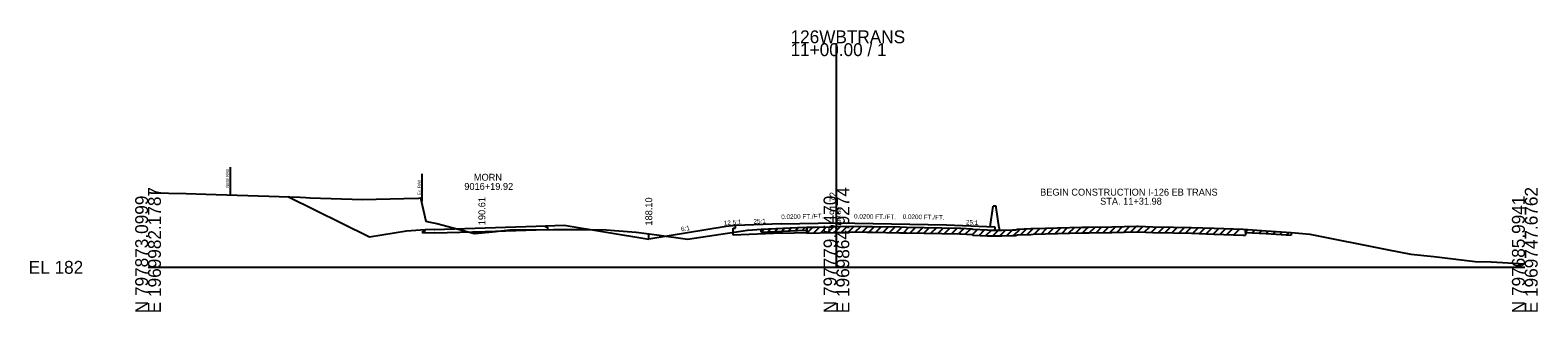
# Model space of a CAD drawing. Extents: x -6494 to 1970605, y -10 to 798140.
# Drawn here: x -25.7 to 302.8, y 3490.3 to 3551.6 of the extents above; entities that cross this region are included whole.
import ezdxf

# ---------------------------------------------------------------- set-up
doc = ezdxf.new("R2010")
doc.units = 0
for name, color, linetype in [('RD_GPK_XS_Cell', 7, 'Continuous'), ('RD_XS_Base', 7, 'Continuous'), ('RD_XS_EarthShd', 7, 'Continuous'), ('RD_XS_ExGround', 7, 'Continuous'), ('RD_XS_ExPaveRet', 7, 'Continuous'), ('RD_XS_ExRW', 7, 'Continuous'), ('RD_XS_MedBWall', 7, 'Continuous'), ('RD_XS_Misc_Line', 7, 'Continuous'), ('RD_XS_NewRW', 7, 'Continuous'), ('RD_XS_Pave', 7, 'Continuous'), ('RD_XS_PaveOvlay', 7, 'Continuous'), ('RD_XS_PaveShd', 7, 'Continuous'), ('RD_XS_TieSlope', 7, 'Continuous'), ('RD_XS_TX_Elev_EX', 7, 'Continuous'), ('RD_XS_TX_Elev_PR', 7, 'Continuous'), ('RD_XS_TX_Misc', 7, 'Continuous'), ('RD_XS_TX_Notes', 7, 'Continuous'), ('RD_XS_TX_Profile', 7, 'Continuous'), ('RD_XS_TX_ShdSlope', 7, 'Continuous'), ('RD_XS_TX_Slope', 7, 'Continuous'), ('RD_XS_TX_Station', 7, 'Continuous')]:
    doc.layers.add(name, color=color, linetype=linetype)

msp = doc.modelspace()

# ---------------------------------------------------------------- linework, layer by layer
at = {"layer": 'RD_GPK_XS_Cell'}
for p, q in [((150, 3500), (150, 3548.79)), ((0, 3500), (150, 3500)), ((150, 3500), (300, 3500))]:
    msp.add_line(p, q, dxfattribs=at)
at = {"layer": 'RD_XS_Base'}
for p, q in [((86.62, 3508.72), (86.62, 3509.02)), ((87.13, 3508.74), (86.62, 3508.72)), ((87.13, 3508.26), (87.13, 3508.74)), ((128, 3508.52), (128, 3509.08)), ((59.85, 3507.88), (60.35, 3507.89)), ((59.85, 3507.4), (59.85, 3507.88)), ((62.38, 3507.48), (59.85, 3507.4)), ((60.35, 3507.89), (60.35, 3508.19)), ((84.6, 3508.18), (87.13, 3508.26)), ((127.5, 3508.5), (128, 3508.52)), ((127.5, 3507.02), (127.5, 3508.5)), ((138, 3507.44), (127.5, 3507.02)), ((138, 3507.44), (143.58, 3507.55))]:
    msp.add_line(p, q, dxfattribs=at)
at = {"layer": 'RD_XS_EarthShd'}
for p, q in [((86.62, 3509.02), (90.66, 3509.15)), ((128, 3509.08), (126, 3508.92)), ((60.35, 3508.19), (56.31, 3507.87))]:
    msp.add_line(p, q, dxfattribs=at)
at = {"layer": 'RD_XS_ExGround'}
msp.add_lwpolyline([(0, 3516.26), (0.7, 3516.24), (8.32, 3516.06), (12.61, 3515.95), (33.13, 3515.25), (34.37, 3515.19), (35.3, 3515.16), (46.72, 3514.79), (55.7, 3514.96), (59.03, 3515.02), (59.36, 3515.16), (60.52, 3510.05), (61.1, 3509.93), (62.9, 3509.52), (71.13, 3507.33), (75.08, 3507.71), (78.85, 3508.15), (88.32, 3508.22), (90.16, 3508.22), (94.64, 3508.2), (99.82, 3508.18), (101.66, 3508.03), (106.38, 3507.63), (110.84, 3507.08), (117.51, 3506.16), (126.25, 3507.44), (130.63, 3508.1), (131.69, 3508.16), (133.57, 3508.27), (141.48, 3508.68), (149.27, 3508.84), (150, 3508.86), (153.59, 3508.95), (156.6, 3508.91), (157.85, 3508.89), (163.85, 3508.79), (165.3, 3508.77), (176.78, 3508.52), (177.11, 3508.51), (179.51, 3508.38), (179.75, 3508.27), (182.82, 3508.13), (183.33, 3508.11), (183.75, 3508.11), (186.02, 3508.1), (188.38, 3508.16), (189.02, 3508.18), (189.45, 3508.31), (192.37, 3508.43), (192.9, 3508.45), (203.49, 3508.73), (205.04, 3508.75), (210, 3508.83), (215.43, 3508.94), (215.77, 3508.94), (218.94, 3508.81), (223.44, 3508.73), (227.34, 3508.65), (232.31, 3508.49), (238.6, 3508.27), (243.65, 3507.95), (249.11, 3507.61), (249.93, 3507.54), (253.16, 3507.24), (269.95, 3503.85), (275.19, 3502.88), (280.19, 3502.33), (289.21, 3501.3), (292.69, 3501.16), (300, 3500.73)], dxfattribs=at)
at = {"layer": 'RD_XS_ExPaveRet'}
for p, q in [((133.57, 3507.64), (133.57, 3508.27)), ((133.57, 3507.64), (141.48, 3508.05)), ((141.48, 3508.05), (143.58, 3508.1)), ((143.58, 3507.47), (143.58, 3508.72)), ((143.58, 3508.72), (143.58, 3508.1)), ((143.58, 3507.47), (149.27, 3507.59)), ((149.27, 3507.59), (150, 3507.61)), ((150, 3507.61), (153.59, 3507.7)), ((153.59, 3507.7), (156.6, 3507.66)), ((156.6, 3507.66), (157.85, 3507.64)), ((157.85, 3507.64), (163.85, 3507.54)), ((163.85, 3507.54), (165.3, 3507.52)), ((165.3, 3507.52), (176.78, 3507.27)), ((176.78, 3507.27), (177.11, 3507.26)), ((177.11, 3507.26), (179.51, 3507.13)), ((179.51, 3507.13), (179.75, 3507.02)), ((179.75, 3507.02), (182.82, 3506.88)), ((182.82, 3506.88), (183.33, 3506.86)), ((183.33, 3506.86), (183.75, 3506.86)), ((183.75, 3506.86), (186.02, 3506.85)), ((186.02, 3506.85), (188.38, 3506.91)), ((188.38, 3506.91), (189.02, 3506.93)), ((189.02, 3506.93), (189.45, 3507.06)), ((189.45, 3507.06), (192.37, 3507.18)), ((192.37, 3507.18), (192.9, 3507.2)), ((192.9, 3507.2), (203.49, 3507.48)), ((203.49, 3507.48), (205.04, 3507.5)), ((205.04, 3507.5), (210, 3507.58)), ((210, 3507.58), (215.43, 3507.69)), ((215.43, 3507.69), (215.77, 3507.69)), ((215.77, 3507.69), (218.94, 3507.56)), ((218.94, 3507.56), (223.44, 3507.48)), ((223.44, 3507.48), (227.34, 3507.4)), ((227.34, 3507.4), (232.31, 3507.24)), ((232.31, 3507.24), (238.6, 3507.02)), ((238.6, 3507.02), (239.11, 3506.98)), ((239.11, 3508.23), (239.11, 3506.98)), ((239.11, 3507.61), (239.11, 3508.23)), ((239.11, 3507.61), (243.65, 3507.33)), ((243.65, 3507.33), (249.11, 3506.98)), ((249.11, 3507.61), (249.11, 3506.98))]:
    msp.add_line(p, q, dxfattribs=at)
at = {"layer": 'RD_XS_ExRW'}
msp.add_line((59.68, 3520.37), (59.68, 3514.37), dxfattribs=at)
at = {"layer": 'RD_XS_MedBWall'}
for p, q in [((183.48, 3508.84), (184.15, 3513.32)), ((184.81, 3513.32), (184.15, 3513.32)), ((184.81, 3513.04), (184.81, 3513.32)), ((185.48, 3508.56), (184.81, 3513.04)), ((185.48, 3508.56), (185.48, 3508.1))]:
    msp.add_line(p, q, dxfattribs=at)
at = {"layer": 'RD_XS_Misc_Line'}
for p, q in [((143.58, 3507.47), (144.85, 3508.75)), ((145.08, 3507.5), (146.35, 3508.78)), ((146.58, 3507.54), (147.85, 3508.81)), ((148.08, 3507.57), (149.35, 3508.84)), ((149.58, 3507.6), (150.86, 3508.88)), ((151.08, 3507.64), (152.36, 3508.92)), ((152.58, 3507.67), (153.85, 3508.94)), ((154.08, 3507.69), (155.31, 3508.92)), ((155.58, 3507.67), (156.81, 3508.9)), ((157.08, 3507.65), (158.31, 3508.88)), ((158.58, 3507.63), (159.81, 3508.86)), ((160.08, 3507.6), (161.31, 3508.83)), ((161.58, 3507.58), (162.81, 3508.81)), ((163.08, 3507.55), (164.31, 3508.78)), ((164.58, 3507.53), (165.81, 3508.76)), ((203.59, 3507.48), (204.86, 3508.75)), ((205.09, 3507.5), (206.36, 3508.77)), ((206.59, 3507.53), (207.86, 3508.8)), ((208.09, 3507.55), (209.36, 3508.82)), ((209.59, 3507.58), (210.86, 3508.85)), ((211.09, 3507.6), (212.36, 3508.88)), ((212.59, 3507.63), (213.87, 3508.91)), ((214.09, 3507.66), (215.37, 3508.93)), ((215.59, 3507.69), (216.8, 3508.9)), ((217.09, 3507.64), (218.29, 3508.84)), ((218.59, 3507.58), (219.81, 3508.8)), ((220.09, 3507.54), (221.32, 3508.77)), ((221.59, 3507.52), (222.82, 3508.74)), ((133.57, 3507.64), (134.23, 3508.3)), ((135.07, 3507.72), (135.73, 3508.38)), ((136.57, 3507.8), (137.23, 3508.46)), ((138.07, 3507.88), (138.73, 3508.53)), ((139.57, 3507.95), (140.23, 3508.61)), ((141.08, 3508.03), (141.73, 3508.68)), ((142.58, 3508.08), (143.21, 3508.71)), ((166.08, 3507.5), (167.3, 3508.72)), ((167.58, 3507.47), (168.8, 3508.69)), ((169.08, 3507.44), (170.3, 3508.66)), ((170.58, 3507.4), (171.81, 3508.63)), ((172.08, 3507.37), (173.31, 3508.59)), ((173.58, 3507.34), (174.81, 3508.56)), ((175.08, 3507.31), (176.31, 3508.53)), ((176.58, 3507.27), (177.78, 3508.48)), ((178.08, 3507.21), (179.27, 3508.4)), ((179.58, 3507.1), (180.71, 3508.23)), ((181.08, 3506.96), (182.28, 3508.16)), ((182.58, 3506.89), (183.8, 3508.11)), ((184.08, 3506.86), (185.33, 3508.1)), ((185.58, 3506.85), (186.85, 3508.12)), ((187.08, 3506.87), (188.37, 3508.16)), ((188.59, 3506.91), (190, 3508.33)), ((190.09, 3507.08), (191.39, 3508.39)), ((191.59, 3507.15), (192.88, 3508.45)), ((193.09, 3507.2), (194.37, 3508.49)), ((194.59, 3507.24), (195.87, 3508.53)), ((196.09, 3507.28), (197.37, 3508.57)), ((197.59, 3507.32), (198.87, 3508.6)), ((199.09, 3507.36), (200.37, 3508.64)), ((200.59, 3507.4), (201.87, 3508.68)), ((202.09, 3507.44), (203.37, 3508.72)), ((223.09, 3507.49), (224.32, 3508.71)), ((224.59, 3507.46), (225.82, 3508.68)), ((226.09, 3507.43), (227.32, 3508.65)), ((227.59, 3507.39), (228.8, 3508.6)), ((229.09, 3507.34), (230.3, 3508.55)), ((230.59, 3507.29), (231.8, 3508.5)), ((232.09, 3507.24), (233.3, 3508.45)), ((233.6, 3507.19), (234.8, 3508.4)), ((235.1, 3507.14), (236.3, 3508.35)), ((236.6, 3507.09), (237.8, 3508.29)), ((239.11, 3507.61), (239.7, 3508.2)), ((240.61, 3507.52), (241.2, 3508.11)), ((242.11, 3507.42), (242.7, 3508.01)), ((243.61, 3507.33), (244.2, 3507.92)), ((245.11, 3507.24), (245.7, 3507.82)), ((246.61, 3507.14), (247.2, 3507.73)), ((248.11, 3507.05), (248.7, 3507.63))]:
    msp.add_line(p, q, dxfattribs=at)
at = {"layer": 'RD_XS_NewRW'}
msp.add_line((17.88, 3521.77), (17.88, 3515.77), dxfattribs=at)
at = {"layer": 'RD_XS_Pave'}
for p, q in [((73.49, 3508.61), (84.6, 3508.96)), ((138, 3509.48), (150, 3509.72)), ((150, 3509.72), (174, 3509.24)), ((62.38, 3508.26), (73.49, 3508.61)), ((62.38, 3507.48), (73.49, 3507.83)), ((73.49, 3507.83), (84.6, 3508.18))]:
    msp.add_line(p, q, dxfattribs=at)
at = {"layer": 'RD_XS_PaveOvlay'}
for p, q in [((143.58, 3508.72), (149.27, 3508.84)), ((149.27, 3508.84), (150, 3508.86)), ((150, 3508.86), (153.59, 3508.95)), ((153.59, 3508.95), (156.6, 3508.91)), ((156.6, 3508.91), (157.85, 3508.89)), ((157.85, 3508.89), (163.85, 3508.79)), ((163.85, 3508.79), (165.3, 3508.77)), ((165.3, 3508.77), (176.78, 3508.52)), ((143.58, 3508.72), (143.58, 3507.55)), ((176.78, 3508.52), (177.11, 3508.51)), ((177.11, 3508.51), (179.51, 3508.38)), ((179.51, 3508.38), (179.75, 3508.27)), ((179.75, 3508.27), (182.82, 3508.13)), ((182.82, 3508.13), (183.33, 3508.11)), ((183.33, 3508.11), (183.75, 3508.11)), ((183.75, 3508.11), (184.48, 3508.11))]:
    msp.add_line(p, q, dxfattribs=at)
at = {"layer": 'RD_XS_PaveShd'}
for p, q in [((84.6, 3508.96), (86.62, 3509.02)), ((138, 3509.48), (128, 3509.08)), ((174, 3509.24), (184.48, 3508.82)), ((184.48, 3508.82), (184.48, 3508.11)), ((62.38, 3508.26), (60.35, 3508.19))]:
    msp.add_line(p, q, dxfattribs=at)
at = {"layer": 'RD_XS_TieSlope'}
for p, q in [((48.23, 3506.54), (30.44, 3515.34)), ((90.66, 3509.15), (109.11, 3506.1)), ((126, 3508.92), (109.11, 3506.1)), ((56.31, 3507.87), (48.23, 3506.54)), ((109.11, 3506.1), (109.11, 3507.29))]:
    msp.add_line(p, q, dxfattribs=at)

# ---------------------------------------------------------------- texts
at = {"layer": 'RD_GPK_XS_Cell'}
for s, p in [('126WBTRANS', (140, 3548.79)), ('11+00.00 / 1', (140, 3545.99)), ('EL 182', (-26, 3498.6))]:
    msp.add_text(s, height=2.8, dxfattribs=at).set_placement(p)
for s, p in [('N 797873.0999', (0, 3490)), ('E 1969982.1787', (2.8, 3490)), ('N 797779.5470', (150, 3490)), ('E 1969864.9274', (152.8, 3490)), ('N 797685.9941', (300, 3490)), ('E 1969747.6762', (302.8, 3490))]:
    msp.add_text(s, height=2.8, rotation=90, dxfattribs=at).set_placement(p)
at = {"layer": 'RD_XS_ExRW'}
msp.add_text('Ex. R/W ', height=0.65, rotation=90, dxfattribs=at).set_placement((59.43, 3515.75))
at = {"layer": 'RD_XS_NewRW'}
msp.add_text('NEW R/W ', height=0.65, rotation=90, dxfattribs=at).set_placement((17.61, 3517.32))
at = {"layer": 'RD_XS_TX_Elev_EX'}
msp.add_text('190.86', height=1, rotation=90, dxfattribs=at).set_placement((151, 3508.86))
at = {"layer": 'RD_XS_TX_Elev_PR'}
for s, p in [(' 191.72', (150, 3509.72)), (' 190.61', (73.49, 3508.61))]:
    msp.add_text(s, height=1.5, rotation=90, dxfattribs=at).set_placement(p)
at = {"layer": 'RD_XS_TX_Misc'}
msp.add_text('188.10', height=1.5, rotation=90, dxfattribs=at).set_placement((109.86, 3509.09))
at = {"layer": 'RD_XS_TX_Notes'}
for s, p in [('BEGIN CONSTRUCTION I-126 EB TRANS', (194.39, 3515.61)), ('STA. 11+31.98', (207.46, 3513.64))]:
    msp.add_text(s, height=1.5, dxfattribs=at).set_placement(p)
at = {"layer": 'RD_XS_TX_Profile'}
for rotation, p in [(2.2906, (131.94, 3509.49)), (357.7094, (178.2, 3509.32))]:
    msp.add_text('25:1', height=1, rotation=rotation, dxfattribs=at).set_placement(p)
at = {"layer": 'RD_XS_TX_ShdSlope'}
msp.add_text('12.5:1', height=1, rotation=4.5739, dxfattribs=at).set_placement((125.5, 3509.13))
at = {"layer": 'RD_XS_TX_Slope'}
for s, rotation, p in [('6:1', 9.4623, (116.22, 3507.8)), ('0.0200 FT./FT.', 1.1458, (137.98, 3510.48)), ('0.0200 FT./FT.', 358.8542, (153.83, 3510.64)), ('0.0200 FT./FT.', 358.8542, (164.43, 3510.55))]:
    msp.add_text(s, height=1, rotation=rotation, dxfattribs=at).set_placement(p)
at = {"layer": 'RD_XS_TX_Station'}
for s, p in [('MORN', (70.99, 3518.86)), ('9016+19.92', (68.91, 3516.86))]:
    msp.add_text(s, height=1.5, dxfattribs=at).set_placement(p)

doc.saveas('drawing.dxf')
